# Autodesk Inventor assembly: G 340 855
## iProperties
Company: Mayer & Müller AG Schaltgeräte
Created: 2006-01
Part Number: G 340 855
Material: genietet
Description: Kontaktträger, kompl.
Document SubType Name: Weldment
Designer: I.Baliuc
Manufacturer: Standard
Standards Organization: Custom
Mass: 110.687 g
Surface Area: 152.156 cm^2
Volume: 14.0163 cm^3
Density: 7.89704 g/cm^3
Author: T.Messerschmitt
Revision Number: 340855
